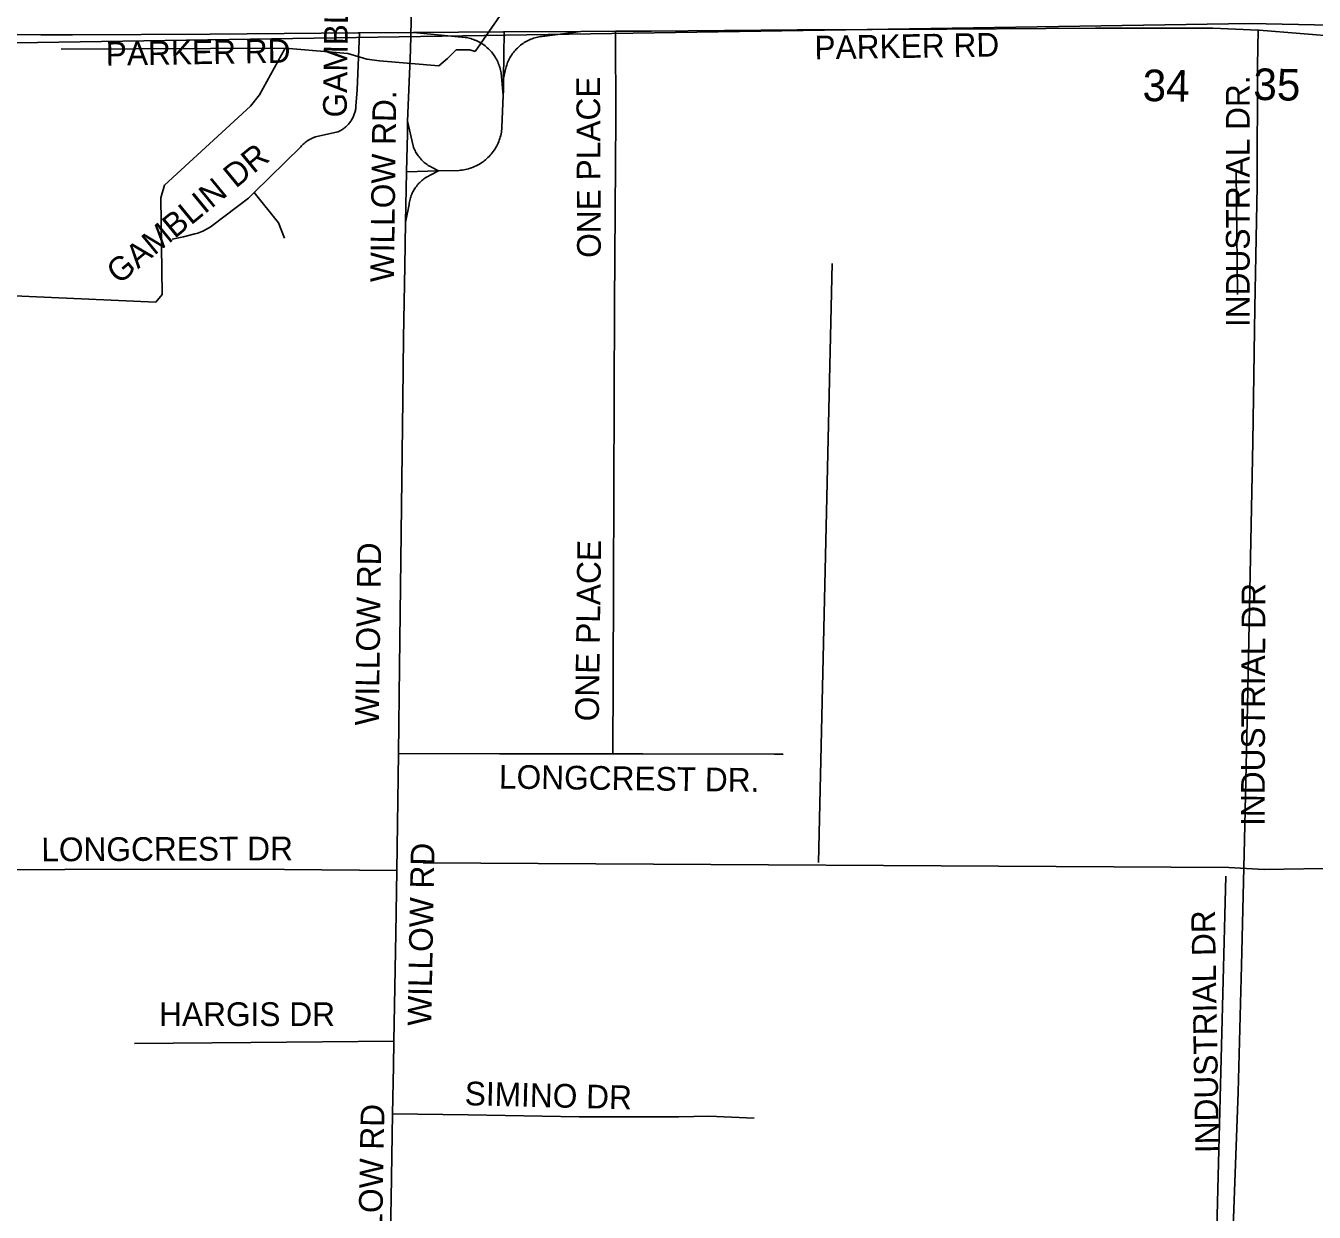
# Model space of a CAD drawing. Extents: x 1670563 to 1761545, y 515755 to 578944.
# Drawn here: x 1711032 to 1715113, y 535267 to 539024 of the extents above; entities that cross this region are included whole.
import ezdxf

# ---------------------------------------------------------------- set-up
doc = ezdxf.new("R2010")
doc.units = 0
for name, color, linetype in [('5_sectionlines', 7, 'Continuous'), ('62_text', 7, 'Continuous'), ('SHP_LINE', 7, 'Continuous'), ('STREETCL', 7, 'Continuous'), ('STRNAMES', 7, 'Continuous')]:
    doc.layers.add(name, color=color, linetype=linetype)

msp = doc.modelspace()

# ---------------------------------------------------------------- linework, layer by layer
at = {"layer": '5_sectionlines'}
for p, q in [((1714864.9, 538561), (1714869.8, 538172.6)), ((1714833, 536331), (1714766.6, 533721.4))]:
    msp.add_line(p, q, dxfattribs=at)
msp.add_lwpolyline([(1705537.2, 538907), (1709520.2, 538946.1), (1714908.5, 539031), (1716909.4, 538990.1)], dxfattribs=at)
at = {"layer": 'SHP_LINE'}
for points in [[(1712455, 538942), (1712700, 539296)], [(1710901, 538173), (1711444, 538149), (1711464, 538173), (1711460, 538479), (1711472, 538519), (1711744, 538769), (1711772, 538805), (1711854, 538953)], [(1711144, 538950), (1711854, 538953)], [(1711854, 538953), (1712052, 538936)], [(1712052, 538936), (1712112, 538918), (1712152, 538913), (1712340, 538897), (1712368, 538920), (1712395, 538947), (1712438, 538947), (1712455, 538942)], [(1713543, 536374), (1713586, 538271)], [(1712291, 536373), (1714842, 536359), (1714954, 536352), (1716205, 536373), (1716459, 536366), (1716534, 536345)]]:
    msp.add_lwpolyline(points, dxfattribs=at)
at = {"layer": 'STREETCL'}
for points in [[(1712241.5, 538721.5), (1712250.1, 538946.9), (1712254.6, 539134.5), (1712259.8, 539433.9), (1712261.1, 539531.6)], [(1712900.1, 539006.3), (1713013.4, 539006.9), (1713476.4, 539010.4), (1713949.1, 539012.5), (1714420.3, 539016), (1714791.9, 539016.5), (1714934.7, 539010.1)], [(1707862.6, 538946.7), (1707924, 538950.9), (1708315.2, 538960.5), (1708805.4, 538972.3), (1709288.2, 538983), (1709525.3, 538989), (1709757, 538992.6), (1710231.3, 538999.3), (1710702.5, 539000.3), (1711079.7, 538994.7), (1711179.8, 538995.2), (1711616.2, 538996.7), (1712085.3, 539000.8), (1712089, 539000.8)], [(1712089, 539000.8), (1712081.4, 538821.2), (1712077.7, 538768.6), (1712077.5, 538765.4), (1712077.1, 538762.2), (1712076.6, 538759), (1712076, 538755.8), (1712075.2, 538752.6), (1712074.4, 538749.5), (1712073.5, 538746.4), (1712072.5, 538743.3), (1712071.3, 538740.2), (1712070.1, 538737.2), (1712068.7, 538734.3), (1712067.3, 538731.4), (1712065.8, 538728.5), (1712064.1, 538725.7), (1712062.4, 538722.9), (1712060.6, 538720.3), (1712058.6, 538717.6), (1712056.6, 538715.1), (1712054.6, 538712.6), (1712052.4, 538710.2), (1712050.1, 538707.8), (1712047.8, 538705.6), (1712045.4, 538703.4), (1712042.9, 538701.3), (1712040.4, 538699.3), (1712037.8, 538697.3), (1712035.1, 538695.5), (1712032.3, 538693.7), (1712029.6, 538692.1), (1712026.7, 538690.5), (1712023.8, 538689.1), (1712020.8, 538687.7), (1711949.9, 538671.8), (1711946.3, 538670.5), (1711942.8, 538669.1), (1711939.3, 538667.6), (1711935.9, 538665.9), (1711932.5, 538664.2), (1711929.2, 538662.3), (1711925.9, 538660.3), (1711922.8, 538658.2), (1711919.7, 538656), (1711916.7, 538653.7), (1711913.7, 538651.3), (1711910.9, 538648.8), (1711908.1, 538646.2), (1711905.4, 538643.5), (1711902.8, 538640.7), (1711756, 538496.2)], [(1712089, 539000.8), (1712260.3, 539002.2)], [(1712260.3, 539002.2), (1712544.8, 539004.4), (1712547.2, 539004.4)], [(1712260.3, 539002.2), (1712423.3, 538986.8), (1712427.8, 538986.1), (1712432.4, 538985.2), (1712436.9, 538984.2), (1712441.4, 538983), (1712445.9, 538981.6), (1712450.3, 538980.1), (1712454.6, 538978.5), (1712458.9, 538976.7), (1712463.1, 538974.7), (1712467.2, 538972.6), (1712471.3, 538970.4), (1712475.3, 538968), (1712479.2, 538965.5), (1712483, 538962.8), (1712486.7, 538960), (1712490.4, 538957.1), (1712493.9, 538954.1), (1712497.3, 538951), (1712500.6, 538947.7), (1712503.8, 538944.3), (1712506.9, 538940.8), (1712509.8, 538937.2), (1712512.6, 538933.5), (1712515.3, 538929.8), (1712517.9, 538925.9), (1712520.3, 538921.9), (1712522.6, 538917.9), (1712524.8, 538913.8), (1712526.8, 538909.6), (1712528.6, 538905.3), (1712530.3, 538901), (1712531.9, 538896.6), (1712533.3, 538892.2), (1712534.5, 538887.7), (1712535.6, 538883.2), (1712536.6, 538878.6), (1712537.4, 538874.1), (1712544.3, 538804.2)], [(1712545.4, 538857.1), (1712547.2, 539004.4)], [(1712545.6, 538857.1), (1712550.7, 538880.6), (1712551.6, 538885.1), (1712552.6, 538889.6), (1712553.8, 538894.1), (1712555.2, 538898.5), (1712556.7, 538902.9), (1712558.3, 538907.3), (1712560.1, 538911.5), (1712562, 538915.7), (1712564.1, 538919.9), (1712566.4, 538923.9), (1712568.7, 538927.9), (1712571.2, 538931.8), (1712573.9, 538935.6), (1712576.7, 538939.3), (1712579.6, 538942.9), (1712582.6, 538946.4), (1712585.7, 538949.8), (1712589, 538953.1), (1712592.4, 538956.3), (1712595.8, 538959.3), (1712599.4, 538962.3), (1712603.1, 538965.1), (1712606.9, 538967.8), (1712610.8, 538970.3), (1712614.7, 538972.7), (1712618.8, 538975), (1712622.9, 538977.1), (1712627.1, 538979.1), (1712631.3, 538980.9), (1712635.6, 538982.6), (1712640, 538984.2), (1712644.4, 538985.5), (1712648.9, 538986.8), (1712653.4, 538987.8), (1712657.9, 538988.8), (1712662.5, 538989.5), (1712667.1, 538990.1), (1712671.7, 538990.6), (1712676.3, 538990.8), (1712790.5, 539005.7)], [(1712547.2, 539004.4), (1712790.5, 539005.7)], [(1712790.5, 539005.7), (1712900.1, 539006.3)], [(1712891, 536718.4), (1712892.7, 536955.5), (1712893.3, 537252.8), (1712894.9, 537550.1), (1712896, 537848), (1712896.5, 538143.7), (1712898.7, 538437.8), (1712900.8, 538732.4), (1712900.1, 539006.3)], [(1714826.7, 533731.9), (1714819, 533816.9), (1714814, 533924.1), (1714811.9, 534120.3), (1714812.6, 534198.3), (1714817.6, 534315.1), (1714821.5, 534403.1), (1714826.5, 534511.3), (1714841.5, 534849), (1714856.8, 535248.4), (1714871.3, 535647.8), (1714881.9, 536048), (1714891.8, 536446.7), (1714901, 536868.2), (1714909.4, 537287.4), (1714917.8, 537705.1), (1714924.6, 538130.4), (1714931.6, 538515.9), (1714933, 538897.9), (1714934.7, 539010.1)], [(1714934.7, 539010.1), (1714937.8, 539009.9), (1715198.2, 538988.5)], [(1712544.3, 538804.2), (1712544.8, 538816.8), (1712545.4, 538857.1)], [(1712339, 538564), (1712404.3, 538565.7), (1712409.4, 538566.2), (1712414.5, 538566.8), (1712419.5, 538567.6), (1712424.6, 538568.6), (1712429.5, 538569.7), (1712434.5, 538571), (1712439.4, 538572.5), (1712444.2, 538574.2), (1712449, 538576), (1712453.7, 538578), (1712458.3, 538580.1), (1712462.9, 538582.5), (1712467.4, 538584.9), (1712471.8, 538587.6), (1712476, 538590.4), (1712480.2, 538593.3), (1712484.3, 538596.4), (1712488.3, 538599.6), (1712492.2, 538602.9), (1712495.9, 538606.4), (1712499.5, 538610), (1712503, 538613.8), (1712506.4, 538617.6), (1712509.6, 538621.6), (1712512.7, 538625.7), (1712515.6, 538629.9), (1712518.4, 538634.2), (1712521, 538638.5), (1712523.5, 538643), (1712525.8, 538647.6), (1712528, 538652.2), (1712530, 538656.9), (1712531.8, 538661.7), (1712533.5, 538666.5), (1712535, 538671.4), (1712536.3, 538676.4), (1712537.4, 538681.3), (1712538.4, 538686.4), (1712539.2, 538691.4), (1712539.8, 538696.5), (1712540.3, 538701.6), (1712544.3, 538804.2)], [(1712238.2, 538561.4), (1712240.6, 538682.3), (1712241.5, 538721.5)], [(1712339, 538564), (1712317.4, 538575.8), (1712313.9, 538577.7), (1712310.4, 538579.6), (1712307, 538581.7), (1712303.7, 538583.9), (1712300.4, 538586.2), (1712297.3, 538588.6), (1712294.2, 538591.1), (1712291.2, 538593.8), (1712288.3, 538596.5), (1712285.5, 538599.3), (1712282.8, 538602.2), (1712280.2, 538605.2), (1712277.6, 538608.3), (1712275.2, 538611.5), (1712272.9, 538614.7), (1712270.8, 538618.1), (1712268.7, 538621.5), (1712266.7, 538624.9), (1712264.9, 538628.5), (1712263.2, 538632.1), (1712261.6, 538635.7), (1712260.1, 538639.4), (1712258.8, 538643.2), (1712241.5, 538721.5)], [(1712339, 538564), (1712299.3, 538543.5), (1712295.9, 538541.2), (1712292.5, 538538.7), (1712289.3, 538536.2), (1712286.1, 538533.5), (1712283, 538530.7), (1712280, 538527.8), (1712277.2, 538524.8), (1712274.4, 538521.7), (1712271.7, 538518.5), (1712269.2, 538515.2), (1712266.8, 538511.9), (1712264.5, 538508.4), (1712262.3, 538504.9), (1712260.2, 538501.3), (1712258.2, 538497.6), (1712256.4, 538493.9), (1712254.7, 538490.1), (1712253.2, 538486.3), (1712251.8, 538482.4), (1712250.5, 538478.4), (1712249.3, 538474.4), (1712248.3, 538470.4), (1712247.5, 538466.3), (1712246.7, 538462.3), (1712246.1, 538458.1), (1712235, 538400.8)], [(1712238.2, 538561.4), (1712339, 538564)], [(1712235, 538400.8), (1712238.2, 538561.4)], [(1711756, 538496.2), (1711737.1, 538477.6), (1711625, 538392.5), (1711620.7, 538389.4), (1711616.2, 538386.3), (1711611.7, 538383.4), (1711607.1, 538380.7), (1711602.3, 538378.1), (1711597.5, 538375.7), (1711592.7, 538373.4), (1711587.7, 538371.3), (1711582.7, 538369.3), (1711577.6, 538367.5), (1711572.5, 538365.9), (1711567.3, 538364.5), (1711531.8, 538355.8), (1711496, 538348.2)], [(1711756, 538496.2), (1711832.7, 538400.2), (1711851.3, 538350.8)], [(1712212.7, 536719.4), (1712216.2, 536994), (1712221.5, 537416.9), (1712226.1, 537840.4), (1712228.4, 538035.8), (1712232.2, 538262.5), (1712235, 538400.8)], [(1712207.2, 536349.1), (1712210.8, 536569.7), (1712212.7, 536719.4)], [(1712212.7, 536719.4), (1712532, 536718.8), (1712891, 536718.4)], [(1712891, 536718.4), (1712986.6, 536718.2), (1713402.1, 536717.7), (1713431, 536717.7)], [(1710807.6, 536351.2), (1711155.9, 536352), (1711502.8, 536353.1), (1711851.1, 536352.3), (1712207.2, 536349.1)], [(1712197.7, 535808.4), (1712204, 536149.2), (1712207.2, 536349.1)], [(1712197.7, 535808.4), (1711744.7, 535804.3), (1711376.4, 535801.5)], [(1712193.8, 535578.9), (1712196.3, 535730.1), (1712197.7, 535808.4)], [(1712181, 534886.6), (1712189.4, 535310.4), (1712193.8, 535578.9)], [(1712193.8, 535578.9), (1712433.1, 535575.9), (1712784.3, 535568.8), (1713100.1, 535569.2), (1713195.6, 535571), (1713338.9, 535564.8)]]:
    msp.add_lwpolyline(points, dxfattribs=at)

# ---------------------------------------------------------------- texts
at = {"layer": '62_text'}
for s, p in [('34', (1714568.3, 538785.5)), ('35', (1714919.1, 538789))]:
    msp.add_text(s, height=100, rotation=358.9328, dxfattribs=at).set_placement(p)
at = {"layer": 'STRNAMES'}
for s, rotation, p in [('GAMBLIN DR.', 89.251, (1712048.3, 538732.9)), ('PARKER RD', 0.9613, (1711286.1, 538897.1)), ('PARKER RD', 0.9613, (1713530.4, 538916.8)), ('ONE PLACE', 90.251, (1712853.3, 538289)), ('INDUSTRIAL DR.', 90, (1714908, 538069.7)), ('WILLOW RD.', 89.251, (1712197.9, 538211.3)), ('GAMBLIN DR', 39.4438, (1711327.2, 538202.6)), ('WILLOW RD', 89.251, (1712150.2, 536807.8)), ('ONE PLACE', 89.251, (1712846.8, 536821.1)), ('INDUSTRIAL DR', 89.8382, (1714955.6, 536490.2)), ('LONGCREST DR.', 359.251, (1712530.4, 536608.8)), ('LONGCREST DR', 0.247, (1711081.5, 536378.2)), ('WILLOW RD', 88.9471, (1712316.3, 535856.8)), ('INDUSTRIAL DR', 91, (1714811.3, 535454.9)), ('SIMINO DR', 358.5699, (1712421.7, 535606.2)), ('WILLOW RD', 88.9471, (1712157.7, 535030))]:
    msp.add_text(s, height=75, rotation=rotation, dxfattribs=at).set_placement(p)
msp.add_text('HARGIS DR', height=75, dxfattribs=at).set_placement((1711454.3, 535856.8))

doc.saveas('drawing.dxf')
